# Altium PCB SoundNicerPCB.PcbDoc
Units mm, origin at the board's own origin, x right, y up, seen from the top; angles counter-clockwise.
Board outline 14.15 x 110.15 mm, 2 copper layers (Top Layer, Bottom Layer); 42 components, 31 nets, 126 pads, 46 vias.
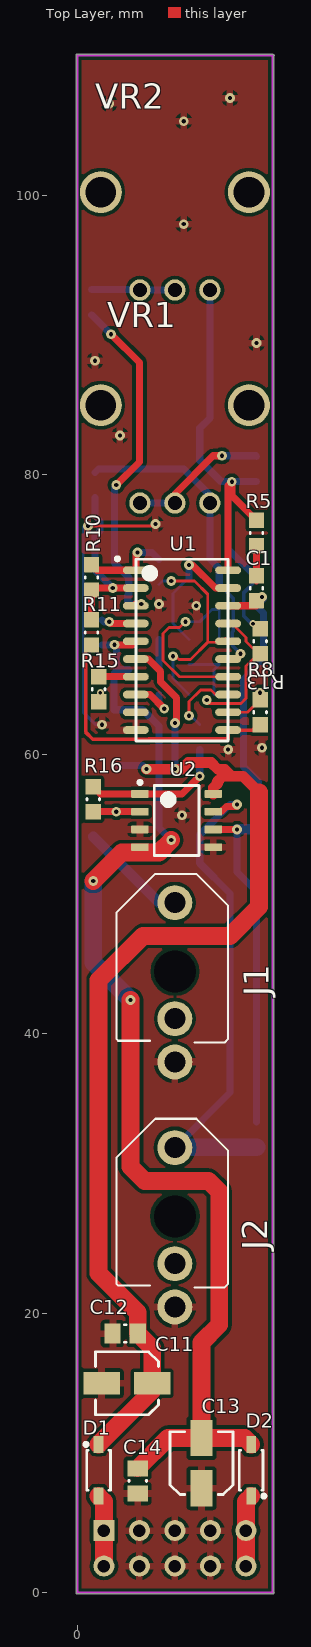
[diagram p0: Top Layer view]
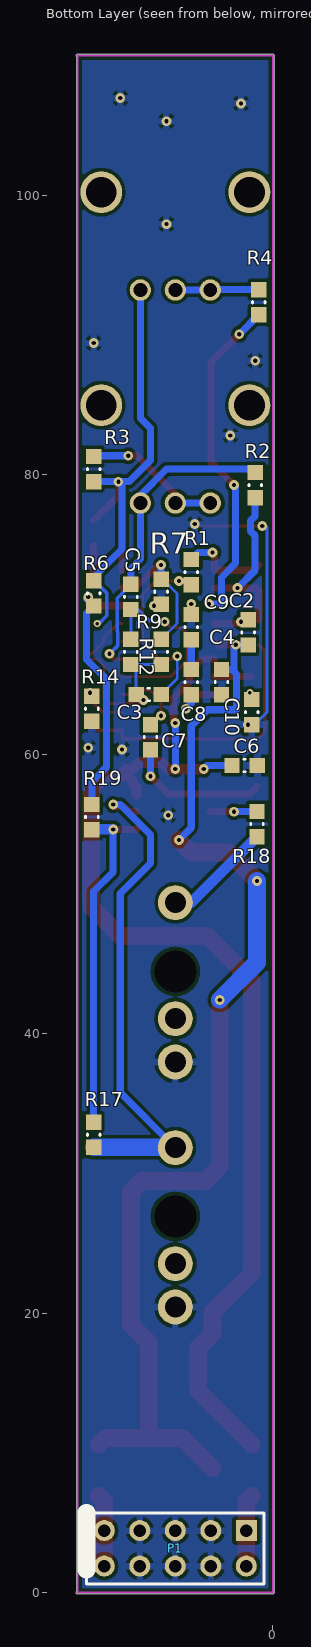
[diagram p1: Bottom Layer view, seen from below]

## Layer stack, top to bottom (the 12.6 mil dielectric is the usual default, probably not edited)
Top Solder: solder mask 0.0102, Solder Resist, Dk 3.5
Top Layer: signal copper 0.0356
Dielectric 1: dielectric 0.32, FR-4, Dk 4.8
Bottom Layer: signal copper 0.0356
Bottom Solder: solder mask 0.0102, Solder Resist, Dk 3.5

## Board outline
-0.077,0 ccw(c0,0) 0,-0.077 14,-0.077 ccw(c14,0) 14.077,0 ccw(c14,0) 14.047,0.061 14.047,109.921 ccw(c14,109.982) 14.077,109.982 ccw(c14,109.982) 14.023,110.055 ccw(c13.97,110) 13.921,110.059 0.049,110.059 ccw(c0,110) -0.077,110

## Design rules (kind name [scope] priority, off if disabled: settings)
Clearance [All] p1: gap=0.254 ignorepadtopadclearanceinfootprint=FALSE except(0: Arc-Hole Track-Hole SMDPad-Hole THPad-Hole Via-Hole Fill-Hole Poly-Hole Region-Hole Text-Hole)
PlaneConnect [All] p1: planeconnectstyle=Relief reliefexpansion=0.508 reliefentries=4 reliefconductorwidth=0.508 reliefairgap=0.254
PolygonConnect [All] p1: connectstyle=Relief reliefconductorwidth=0.508 reliefentries=4 polygonreliefangle="90 Angle" airgapwidth=0.254
RoutingVias [All] p1: holewidth=0.3 width=0.7 viastyle="Through Hole" minholewidth=0.3 minwidth=0.7 maxholewidth=0.711 maxwidth=0.7
SolderMaskExpansion [All] p1: expansion=0.102
Width [All] p1: maxlimit=1.27 minlimit=0.203 preferedwidth=0.508
29 further rules are at their usual default settings.

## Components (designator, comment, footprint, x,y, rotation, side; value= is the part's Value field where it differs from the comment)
C1 "0." CAPC0603(1608)100_M 12.827,71.871 r270 top value=100p
C2 "0." CAPC0603(1608)100_M 1.778,68.707 r90 bottom value=2.2u
C3 "0." CAPC0603(1608)100_M 8.89,64.262 r0 bottom value=3.3n
C4 "0.47uF" CAPC0603(1608)100_M 3.683,65.151 r90 bottom
C5 "0." CAPC0603(1608)100_M 10.16,71.247 r90 bottom value=33n
C6 "0.47uF" CAPC0603(1608)100_M 2.032,59.182 r0 bottom
C7 "0.47uF" CAPC0603(1608)100_M 8.763,61.214 r270 bottom
C8 "0." CAPC0603(1608)100_M 5.842,65.151 r270 bottom value=2.2u
C9 "0." CAPC0603(1608)100_M 5.842,69.088 r270 bottom value=2.2u
C10 "100nF" CAPC0603(1608)100_M 1.524,63.003 r270 bottom
C11 "10uF" NIC-CAPA2-4X5.8_V 3.556,14.986 r180 top
C12 "100nF" CAPC0805(2012)75_N 3.429,18.542 r0 top
C13 "10uF" NIC-CAPA2-4X5.8_V 8.89,9.271 r90 top
C14 "100nF" CAPC0805(2012)75_N 4.318,8.001 r270 top
D1 "1N5819HW-7-F" DIOD-SOD-123-2_V 1.524,8.763 r90 top
D2 "1N5819HW-7-F" DIOD-SOD-123-2_V 12.446,8.763 r270 top
J1 "Thonkicon jack" "Thonkiconn Pot PJ301M" 6.985,44.45 r0 top
J2 "Thonkicon jack" "Thonkiconn Pot PJ301M" 6.985,26.924 r0 top
P1 "Header 5X2" HDR2X5 1.905,4.445 r0 bottom
R1 "21.5k" RESC0603(1608)_M 5.842,73.025 r90 bottom
R2 "21.5k" RESC0603(1608)_M 1.27,79.248 r270 bottom
R3 "13.3k" RESC0603(1608)_M 12.827,80.391 r270 bottom
R4 "13.3k" RESC0603(1608)_M 1.016,92.329 r270 bottom
R5 "10k" RESC0603(1608)_M 12.827,75.819 r90 top
R6 "18.2k" RESC0603(1608)_M 12.827,71.501 r90 bottom
R7 "21.5k" RESC0603(1608)_M 8.001,71.617 r90 bottom
R8 "39.2k" RESC0603(1608)_M 13.081,68.072 r90 top
R9 "21.5k" RESC0603(1608)_M 8.001,67.31 r270 bottom
R10 "21.5k" RESC0603(1608)_M 1.016,72.644 r270 top
R11 "21.5k" RESC0603(1608)_M 1.016,68.707 r270 top
R12 "21.5k" RESC0603(1608)_M 10.16,67.31 r90 bottom
R13 "21.5k" RESC0603(1608)_M 13.081,62.992 r270 top
R14 "21.5k" RESC0603(1608)_M 12.954,63.246 r90 bottom
R15 "10.6k" RESC0603(1608)_M 1.524,64.643 r90 top
R16 "100k" RESC0603(1608)_M 1.143,56.769 r270 top
R17 "100k" RESC0603(1608)_M 12.827,32.766 r90 bottom
R18 "100k" RESC0603(1608)_M 1.143,54.991 r270 bottom
R19 "100k" RESC0603(1608)_M 12.954,55.499 r90 bottom
U1 "V2153 Sound Enhancement IC" "SOIC20 - duplicate" 7.493,67.437 r0 top
U2 "TL072CD" D0008A_L 7.112,55.245 r0 top
VR1 "50k" SonGueiPot 6.985,84.963 r0 top
VR2 "50k" SonGueiPot 6.985,100.203 r0 top

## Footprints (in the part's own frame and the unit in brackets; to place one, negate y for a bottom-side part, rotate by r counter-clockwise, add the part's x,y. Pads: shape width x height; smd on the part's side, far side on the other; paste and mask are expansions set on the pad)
CAPC0603(1608)100_M [mm] "Chip Capacitor, Body 1.6x0.8mm, Height 1.0mm, IPC Low Density"
  rect 1.1x1.1 smd: 1(-0.9,0) 2(0.9,0)
  silkscreen extent -0.05,-0.45 0.05,0.45, body extent -0.87,-0.47 0.88,0.48, height 1
CAPC0805(2012)75_N [mm] "Chip Capacitor, Body 2.0x1.2mm, Height 0.75mm, IPC Medium Density"
  rect 1.15x1.45 smd: 1(-0.9,0) 2(0.9,0)
  silkscreen extent -0.05,-0.62 0.05,0.63, body extent -1.1,-0.72 1.1,0.73, height 0.75
D0008A_L [mm] "SOIC, 8-Leads, Body 5x4mm, Pitch 1.27mm, IPC High Density"
  rrect18% 1.25x0.55 smd: 1(-2.625,1.905) 2(-2.625,0.635) 3(-2.625,-0.635) 4(-2.625,-1.905) 5(2.625,-1.905) 6(2.625,-0.635) 7(2.625,0.635) 8(2.625,1.905)
  silkscreen extent -2.75,-2.5 1.6,2.85, body extent -3,-2.45 3,2.45, height 1.63
DIOD-SOD-123-2_V [mm] "SOD-123, 2-Leads, Body 2.85x1.7mm (max), Pitch 3.7mm"
  rect 1.2x0.7 smd: 1(-1.85,0) 2(1.85,0)
  silkscreen extent -1.43,-0.85 1.97,1.02, body extent -1.42,-0.85 1.43,0.85, height 1.45
HDR2X5 [mm] "Connector; Header; 5x2 Position"
  rect 1.5x1.5 hole 0.9: 1(0,0)
  round 1.5 hole 0.9: 2(0,2.54) 3(2.54,0) 4(2.54,2.54) 5(5.08,0) 6(5.08,2.54) 7(7.62,0) 8(7.62,2.54) 9(10.16,0) 10(10.16,2.54)
  silkscreen extent -1.27,-1.27 11.43,3.81
NIC-CAPA2-4X5.8_V [mm] "Aluminum Electrolytic Capacitor, Diameter 4mm, Height 6.1mm, Pitch 3.6mm"
  rect 2.6x1.6 smd: 1(-1.8,0) 2(1.8,0)
  silkscreen extent -2.25,-2.25 2.25,2.25, body extent -2,-1.98 2,2, height 6.1
RESC0603(1608)_M [mm] "Chip Resistor, Body 1.6x0.8mm, IPC Low Density"
  rect 1.1x1.1 smd: 1(-0.9,0) 2(0.9,0)
  silkscreen extent -0.05,-0.45 0.05,0.45, body extent -0.85,-0.47 0.85,0.47, height 0.6
"SOIC20 - duplicate" [mm]
  oval 1.85x0.55 smd: 1(-3.302,5.715) 2(-3.302,4.445) 3(-3.302,3.175) 4(-3.302,1.905) 5(-3.302,0.635) 6(-3.302,-0.635) 7(-3.302,-1.905) 8(-3.302,-3.175) 9(-3.302,-4.445) 10(-3.302,-5.715) 11(3.302,-5.715) 12(3.302,-4.445) 13(3.302,-3.175) 14(3.302,-1.905) 15(3.302,-0.635) 16(3.302,0.635) 17(3.302,1.905) 18(3.302,3.175) 19(3.302,4.445) 20(3.302,5.715)
  silkscreen extent -4.75,-6.5 3.3,6.66, body extent -3.8,-6.48 3.8,6.48, height 2.65
SonGueiPot [mm]
  round 3 hole 2.2: 0(-5.3,0) 0(5.3,0)
  round 1.524 hole 1: 1(-2.5,-7) 2(0,-7) 3(2.5,-7)
  body extent -4.88,-7.23 4.88,5.32, height 20
"Thonkiconn Pot PJ301M" [mm] "PJ301 Thonkicon Jack from Thonk"
  round 1.524 hole 3: 0(0,0)
  round 2.5 hole 1.5: 1(0,-6.48) 2(0,-3.38) 3(0,4.92)
  silkscreen extent -4.19,-5.08 3.81,6.98, body extent -4.55,-10.29 4.44,5.71, height 14

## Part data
C1: library part CMP-1035-00002-1, "CAP", Case-EIA=0603, Mfr=AVX, Mfr_Pn=06032A101JAT2A
C2 C8 C9: library part CMP-1035-00002-1, "CAP", Case-EIA=0603, Mfr=Murata, Mfr_Pn=GRM188R61E225KA12D
C3: library part CMP-1035-00002-1, "CAP", Case-EIA=0603, Mfr=AVX, Mfr_Pn=06035A332JAT2A
C4 C6 C7: library part CMP-1035-00002-1, "CAP", Mfr=Murata, Mfr_Pn=GCM188R71E474KA64J
C5: library part CMP-1035-00002-1, "CAP", Case-EIA=0603, Mfr=Murata, Mfr_Pn=GRM188R71H333KA61D
C10: library part CMP-1035-00002-1, "CAP", Mfr=AVX, Mfr_Pn=MM035C104KCZ2A
C11 C13: library part CMP-0687-00016-1, "Aluminum Electrolytic Capacitor, UD Series, Low Impedance, 10 uF, 25 V, + / - 20%, -55 to 105 degC, Chip Type, 4 x 5.8 mm D x L, Pb-Free, Reel", Mfr=Nichicon, Mfr_Pn=UUD1E100MCL1GS
C12 C14: library part CMP-1036-00012-1, "CAP 0.5pF 25V ±0.1pF 0805 (2012 Metric) Thickness 0.75mm SMD", Mfr=AVX, Mfr_Pn=08053F102K4T2A
D1 D2: library part CMP-0303-00003-1, "1.0 A Surface Mount Schottky Barrier Rectifier, 40 V, -65 to 125 degC, 2-Pin SOD-123 Package, RoHS, Tape and Reel", Mfr="Diodes Inc."
P1: "Header, 5-Pin, Dual row"
R1 R2 R7 R9 R10 R11 R12 R13 R14: library part CMP-1012-00002-1, "Res", Case-EIA=0603, Mfr=Susumu, Mfr_Pn=RG1608P-2152-D-T5, Tolerance="5 %"
R3 R4: library part CMP-1012-00002-1, "Res", Case-EIA=0603, Mfr=Susumu, Mfr_Pn=RR0816P-1332-D-13C, Tolerance="5 %"
R5: library part CMP-1012-00002-1, "Res", Case-EIA=0603, Mfr=Susumu, Mfr_Pn=RR0816P-103-D, Tolerance="5 %"
R6: library part CMP-1012-00002-1, "Res", Case-EIA=0603, Mfr=Susumu, Mfr_Pn=RR0816P-1822-D-26C, Tolerance="5 %"
R8: library part CMP-1012-00002-1, "Res", Case-EIA=0603, Mfr=KOA, Mfr_Pn=RK73H1JTTD3922F, Tolerance="5 %"
R15: library part CMP-1012-00002-1, "Res", Case-EIA=0603, Mfr=Koa, Mfr_Pn=RN73H1JTTD1062D100, Tolerance="5 %"
R16 R17 R18 R19: library part CMP-1012-00002-1, "Res", Case-EIA=0603, Mfr=Susumu, Mfr_Pn=RR0816P-104-D, Tolerance="5 %"
U1: library part CoolaudioV2153, "V2153"
U2: library part CMP-0017-00467-2, "Dual Low-Noise JFET-Input General-Purpose Operational Amplifier, 7 to 36 V, 0 to 70 degC, 8-pin SOIC (D8), Green (RoHS & no Sb/Br)", Manufacturer="Texas Instruments", Rating=Catalog, Total Supply Voltage(Max)(+5V is 5, +/-5V is 10)=36, Total Supply Voltage(Min)(+5V is 5, +/-5V is 10)=7
VR1 VR2: library part CMP-0972-00009-1, "Trimming Potentiometer, 5K Ohm +/- 10%, -55 to 125 degC, 3-Pin 19.05 x 4.83 x 6.6 mm THD, Transparent Housing, RoHS", Manufacturer=Bourns, PartNumber=3006P-7-502ZLF, Resistance (kOhm)=5, Resistance Tolerance="+/- 10%", Temperature Range="-55 to 125 degC"

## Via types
v1: diameter 0.7, hole 0.3, Top Layer to Bottom Layer, tented both sides, 44 vias
v2: diameter 0.508, hole 0.254, Top Layer to Bottom Layer, tented both sides, 2 vias

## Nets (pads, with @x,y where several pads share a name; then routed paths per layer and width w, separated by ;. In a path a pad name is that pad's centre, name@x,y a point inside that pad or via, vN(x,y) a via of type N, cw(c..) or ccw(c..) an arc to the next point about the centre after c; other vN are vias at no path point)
+12V: C6.2 C11.1 C12.2 D1.2 U1.6 U2.8 | length 80.4
  Top Layer w0.508: U1.6 5.08,66.802 5.969,65.913 5.969,65.151 7.112,64.008 7.112,62.357 v1(6.985,62.23)
  Top Layer w0.762: v1(4.953,58.928) v1(6.985,58.928) 7.475,58.928 7.952,59.405 9.574,59.405 10.051,58.928 10.541,58.928 11.049,58.42 ; U2.8 9.737,57.598 10.033,57.894 10.033,58.039 10.414,58.42 11.049,58.42 ; 13.005,57.277 11.862,58.42 11.049,58.42
  Top Layer w1.27: D1.2 C11.1@5.356,14.445 ; C11.1 5.356,17.515 C12.2 4.329,20.055 1.524,22.86 1.524,43.815 4.699,46.99 10.922,46.99 13.005,49.073 13.005,57.277
  Bottom Layer w0.508: C6.2 4.699,59.182 ; v1(6.985,58.928) v1(6.985,62.23)
-12V: C2.1 C4.2 C13.2 C14.1 D2.1 U1.5 U2.4 | length 83.3
  Top Layer w0.508: v1(2.667,67.818) 3.937,67.818 U1.5
  Top Layer w1.27: v1(1.143,50.927) 3.175,52.959 5.842,52.959 v1(6.731,53.848) ; v1(3.81,42.418) 3.81,30.48 4.826,29.464 9.398,29.464 10.16,28.702 10.16,19.177 8.89,17.907 C13.2 ; C14.1 6.488,11.071 C13.2 ; D2.1 11.988,11.071 C13.2
  Bottom Layer w0.508: C2.1 2.656,67.807 v1(2.667,67.818) 2.794,67.691 2.794,65.913 ; C4.2 2.932,66.051 2.794,65.913 ; v1(6.731,53.848) 5.842,54.737 5.842,62.011 4.681,63.172 2.614,63.172 2.614,65.733 2.794,65.913
  Bottom Layer w1.27: v1(1.143,50.927) 1.143,45.085 v1(3.81,42.418)
GND: C4.1 C6.1 C9.1 C10.2 C11.2 C12.1 C13.1 C14.2 J1.1 J2.1 P1.3 P1.4 P1.5 P1.6 P1.7 P1.8 R7.1 R14.1 U1.10 U2.3 U2.5 | length 20.2
  Top Layer w0.203: v1(0.762,76.327) 5.461,76.327 v1(5.588,76.454)
  Bottom Layer w0.203: v1(0.762,76.327) 0.508,76.327 0.432,76.251 0.432,62.992 1.321,62.103 C10.2 v1(1.778,62.103)
  other v1: 7.493,55.626 10.795,60.325 13.208,60.452 8.509,70.612 5.842,70.739 3.048,82.804 1.27,88.138 12.827,89.408 7.62,97.917 7.62,105.283 2.286,106.553 10.922,106.934
NetC1_1: C1.1 R5.1 | length 2.5
  Top Layer w0.508: C1.1@12.827,72.401 R5.1
NetC1_2: C1.2 R6.1 R19.2 U1.18 | length 18.4
  Top Layer w0.508: U1.18 C1.2@12.816,70.612
  Bottom Layer w0.508: R19.2 12.954,58.039 11.896,59.097 11.896,65.33 13.335,66.769 13.335,70.093 R6.1 13.335,71.109 13.208,71.236 v1(13.208,71.247)
NetC2_2: C2.2 U1.4 | length 2.5
  Top Layer w0.508: v1(2.286,69.469) 2.413,69.342 U1.4
  Bottom Layer w0.508: C2.2 1.916,69.469 v1(2.286,69.469)
NetC3_1: C3.1 R1.1 U1.16 | length 15.4
  Top Layer w0.203: v1(6.731,72.39) 8.382,72.39 9.335,71.438 9.335,68.008 ; v1(6.847,67) 7.052,67 7.281,66.771 8.097,66.771 9.335,68.008 ; U1.16 10.604,68.263 10.351,68.008 9.335,68.008
  Bottom Layer w0.203: R1.1 6.107,72.39 v1(6.731,72.39) ; v1(6.847,67) 6.847,65.405 C3.1
NetC3_2: C3.2 R8.1 R9.2 R12.1 U1.17 | length 14.4
  Top Layer w0.203: v1(9.271,63.881) 9.271,63.636 9.275,63.631 11.706,63.631 12.076,64.001 12.076,66.305 12.562,66.791 R8.1@12.954,66.791 ; U1.17 11.067,69.342 12.076,68.333 12.076,68.061 12.965,67.172 R8.1
  Bottom Layer w0.203: R9.2 R12.1 9.79,66.04 C3.2
NetC5_1: C5.1 R12.2 U1.14 | length 14
  Top Layer w0.203: v1(7.747,69.469) 7.325,69.047 6.563,69.047 6.141,68.625 6.141,66.708 7.317,65.532 U1.14 10.771,65.556 U1.14@10.771,65.638
  Bottom Layer w0.203: v1(7.747,69.469) 8.763,69.469 9.641,70.347 C5.1 R12.2
NetC5_2: C5.2 R2.1 U1.15 VR1.3 | length 22.7
  Top Layer w0.254: U1.15 11.43,66.802 11.811,67.183 v1(11.684,67.183)
  Bottom Layer w0.254: C5.2 11.145,71.162 11.145,68.785 11.091,68.731 11.091,67.776 v1(11.684,67.183)
  Bottom Layer w0.508: R2.1 1.513,80.391 7.62,80.391 9.485,78.526 VR1.3 9.485,73.954 10.16,73.279 C5.2
NetC7_1: C7.1 U1.13 | length 5.3
  Top Layer w0.203: v1(8.001,62.738) 8.001,63.754 8.834,64.587 9.563,64.587 9.888,64.262 U1.13
  Bottom Layer w0.203: v1(8.001,62.738) 8.139,62.738 C7.1
NetC7_2: C7.2 R16.1 U2.1 | length 10.3
  Top Layer w0.508: R16.1 1.662,57.15 U2.1 7.493,57.15 v1(8.763,58.42)
  Bottom Layer w0.508: v1(8.763,58.42) C7.2
NetC8_1: C8.1 C9.2 | length 2.1
  Bottom Layer w0.508: C8.1 C9.2
NetC8_2: C8.2 U1.8 | length 3.6
  Top Layer w0.508: U1.8 5.207,64.262 v1(6.223,63.246)
  Bottom Layer w0.508: C8.2 5.842,63.627 v1(6.223,63.246)
NetC10_1: C10.1 R15.1
  other v2: 1.651,64.389
NetD1_1: D1.1 P1.1 P1.2 | length 5.2
  Top Layer w1.27: D1.1 1.905,6.532 P1.1 P1.2
NetD2_2: D2.2 P1.9 P1.10 | length 5.2
  Top Layer w1.27: P1.10 P1.9 12.065,6.532 D2.2
NetJ1_3: J1.3 R18.2 | length 7.8
  Bottom Layer w0.762: R18.2 5.864,49.37 J1.3
NetJ2_3: J2.3 R17.1 U2.7 | length 36.3
  Top Layer w0.508: U2.7 10.287,55.88 10.668,56.261 11.43,56.261 v1(11.43,56.388)
  Bottom Layer w0.508: J2.3 7.007,31.866 10.922,35.781 10.922,50.038 8.763,52.197 8.763,54.229 10.922,56.388 v1(11.43,56.388)
  Bottom Layer w1.27: J2.3@7.007,31.866 R17.1
NetR1_2: R1.2 R10.1 U1.1 | length 6.4
  Top Layer w0.508: R10.1 1.408,73.152 U1.1 4.191,74.295 v1(4.318,74.422)
  Bottom Layer w0.508: v1(4.318,74.422) 5.345,74.422 R1.2
NetR2_2: R2.2 R10.2 R11.1 U1.2 | length 12.7
  Top Layer w0.508: R11.1 R10.2 1.154,71.882 v1(2.54,71.882) U1.2
  Bottom Layer w0.508: R2.2 1.27,77.032 1.62,76.682 1.62,75.972 1.27,75.622 1.27,73.152 v1(2.54,71.882)
NetR3_1: R3.1 VR1.1 VR1.2 | length 10.1
  Top Layer w0.508: VR1.2 6.985,78.613 9.716,81.343 v1(10.351,81.343)
  Bottom Layer w0.508: VR1.1 VR1.2 ; v1(10.351,81.343) 12.774,81.343 R3.1
NetR3_2: R3.2 R5.2 R6.2 R8.2 U1.20 VR2.3 | length 39
  Top Layer w0.508: U1.20 10.795,79.226 v1(11.06,79.491) 11.06,78.486 R5.2
  Bottom Layer w0.254: v2(12.573,69.342) 12.447,69.342 11.896,69.893 11.896,71.532 12.765,72.401 R6.2
  Bottom Layer w0.508: VR2.3 9.485,84.034 8.763,83.312 8.763,81.026 10.298,79.491 v1(11.06,79.491) ; R6.2 12.827,72.644 10.795,74.676 10.795,79.226 v1(11.06,79.491) ; R3.2 v1(11.06,79.491)
NetR4_1: R4.1 VR2.1 VR2.2 | length 6
  Bottom Layer w0.508: R4.1 4.459,93.229 VR2.1 VR2.2
NetR4_2: R4.2 U1.3 | length 24.9
  Top Layer w0.508: v1(2.413,90.043) 4.445,88.011 4.445,80.899 v1(2.794,79.248) ; U1.3 4.118,70.685 4.173,70.739 v1(4.572,70.739)
  Bottom Layer w0.508: R4.2 2.402,90.043 v1(2.413,90.043) ; v1(2.794,79.248) 2.667,79.121 2.667,73.66 3.683,72.644 3.683,71.409 3.61,71.336 3.61,70.685 3.665,70.739 v1(4.572,70.739)
NetR7_2: R7.2 R9.1 U1.19 | length 9.8
  Top Layer w0.508: v1(8.001,73.533) 8.228,73.533 9.879,71.882 U1.19
  Bottom Layer w0.203: R9.1 6.858,69.353 6.858,71.501 7.874,72.517 R7.2
  Bottom Layer w0.508: R7.2 v1(8.001,73.533)
NetR11_2: R11.2 R13.2 U1.11 | length 19.9
  Top Layer w0.254: R11.2 0.593,67.384 0.593,61.586 1.113,61.066 5.113,61.066 5.134,61.087 10.795,61.087 U1.11 12.573,61.722 12.943,62.092 R13.2
NetR13_1: R13.1 R14.2 U1.12 | length 3.2
  Top Layer w0.203: U1.12 12.181,62.992 R13.1 v1(13.081,64.389)
NetR15_2: R15.2 U1.7 | length 2.7
  Top Layer w0.508: R15.2 U1.7@4.18,65.543
NetR16_2: R16.2 R18.1 U2.2 | length 5
  Top Layer w0.508: R16.2@1.154,55.88 v1(2.794,55.88) U2.2
  Bottom Layer w0.508: R18.1@1.154,55.88 v1(2.794,55.88)
NetR17_2: R17.2 R19.1 U2.6 | length 24.7
  Top Layer w0.508: U2.6 v1(11.43,54.61)
  Bottom Layer w0.508: v1(11.43,54.61) 11.43,51.562 12.827,50.165 R17.2
  Bottom Layer w0.762: v1(11.43,54.61) 11.441,54.621 R19.1@12.954,54.621
pads on no net: J1.0 J1.2 J2.0 J2.2 U1.9 VR1.0 VR2.0

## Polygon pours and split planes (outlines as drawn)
GND on Top Layer "Bottom_GND_POUR" (solid, pour order 2): 0,0 0,110 13.97,110 13.97,-0.127 13.843,-0.254
GND on Bottom Layer "Bottom_GND_POUR" (solid, pour order 4): 0,0 13.97,0 13.97,109.855 13.843,109.982 0,109.982

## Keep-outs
Keep-Out Layer:
  lines w0.152: 0,109.982 14,109.982 ; 0,110 0,0 14,0 ; 13.97,0 13.97,110

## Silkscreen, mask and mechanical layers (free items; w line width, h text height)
Bottom Overlay:
  lines w1.27: 13.335,1.651 13.335,5.715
